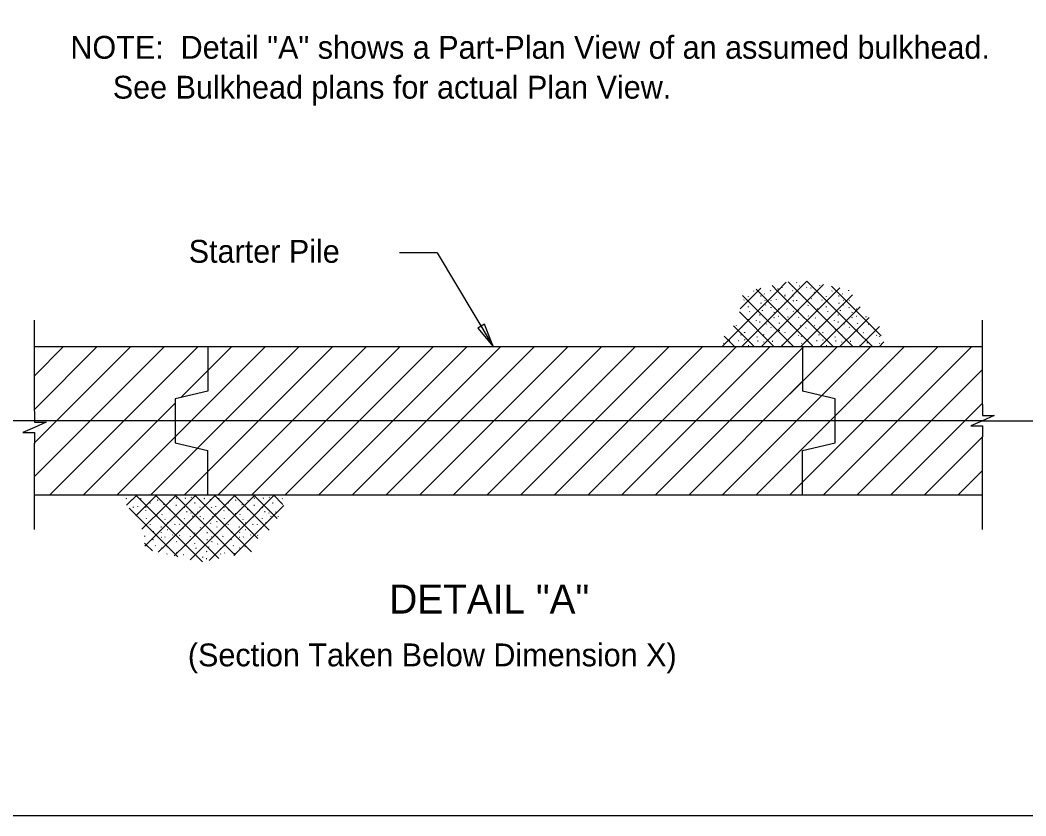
# Model space of a CAD drawing. Extents: x 111162.5 to 111216.6, y 110741.1 to 110776.1.
# Drawn here: x 111166.92 to 111173.58, y 110754.44 to 110759.7 of the extents above; entities that cross this region are included whole.
import ezdxf

# ---------------------------------------------------------------- set-up
doc = ezdxf.new("R2010")
doc.units = 0
for name, color, linetype in [('Patterning', 7, 'Continuous'), ('PlotBorder_dp', 7, 'Continuous'), ('SheetBorder_dp', 7, 'Continuous'), ('TextMisc', 7, 'Continuous'), ('Viewport', 7, 'Continuous')]:
    doc.layers.add(name, color=color, linetype=linetype)

msp = doc.modelspace()

# ---------------------------------------------------------------- linework, layer by layer
at = {"layer": 'Patterning'}
for p, q in [((111169.6835, 110758.1634), (111169.4336, 110758.1634)), ((111169.6835, 110758.1634), (111170.0546, 110757.5448)), ((111167.0161, 110757.1155), (111167.0161, 110757.7198)), ((111173.2935, 110757.1597), (111173.2935, 110757.7198)), ((111173.2935, 110756.3334), (111173.2935, 110756.9491)), ((111167.0161, 110756.3334), (111167.0161, 110756.9048))]:
    msp.add_line(p, q, dxfattribs=at)
msp.add_lwpolyline([(111170.0546, 110757.5448), (111169.9969, 110757.6923), (111169.9515, 110757.6651)], close=True, dxfattribs=at)
for points in [[(111173.2935, 110757.1595), (111173.2935, 110757.087), (111173.371, 110757.087), (111173.2935, 110757.0532), (111173.216, 110757.0195), (111173.2935, 110757.0195), (111173.2935, 110756.947)], [(111167.0161, 110757.1152), (111167.0161, 110757.0427), (111167.0936, 110757.0427), (111167.0161, 110757.009), (111166.9386, 110756.9752), (111167.0161, 110756.9752), (111167.0161, 110756.9027)]]:
    msp.add_lwpolyline(points, dxfattribs=at)
at = {"layer": 'PlotBorder_dp'}
for p, q in [((111167.0161, 110757.5448), (111172.102, 110757.5448)), ((111168.1646, 110757.5448), (111168.1646, 110757.2495)), ((111172.102, 110757.5448), (111172.102, 110757.2495)), ((111172.102, 110757.5448), (111173.2935, 110757.5448)), ((111168.1646, 110757.2495), (111167.948, 110757.1983)), ((111172.3186, 110757.1983), (111172.102, 110757.2495)), ((111167.948, 110757.1983), (111167.948, 110756.9069)), ((111172.3186, 110756.9069), (111172.3186, 110757.1983)), ((111167.948, 110756.9069), (111168.1646, 110756.8558)), ((111172.102, 110756.8558), (111172.3186, 110756.9069)), ((111168.1646, 110756.5605), (111168.1646, 110756.8558)), ((111172.102, 110756.5605), (111172.102, 110756.8558)), ((111172.102, 110756.5605), (111167.0161, 110756.5605)), ((111173.2935, 110756.5605), (111172.102, 110756.5605))]:
    msp.add_line(p, q, dxfattribs=at)
at = {"layer": 'TextMisc'}
for p, q in [((111171.9362, 110757.9116), (111171.9001, 110757.9478)), ((111171.9362, 110757.7813), (111172.1316, 110757.9767)), ((111171.9362, 110757.9116), (111171.9939, 110757.9693)), ((111171.9362, 110757.6511), (111172.2399, 110757.9549)), ((111171.9599, 110757.5445), (111172.3483, 110757.933)), ((111171.9667, 110757.9319), (111171.9675, 110757.9348)), ((111172.4343, 110757.5437), (111172.006, 110757.972)), ((111172.063, 110757.9649), (111172.0638, 110757.9679)), ((111172.0811, 110757.9431), (111172.0788, 110757.9438)), ((111172.1284, 110757.9326), (111172.1299, 110757.9356)), ((111172.4571, 110757.6511), (111172.1315, 110757.9767)), ((111172.1579, 110757.9309), (111172.1586, 110757.934)), ((111172.2167, 110757.9461), (111172.2159, 110757.9476)), ((111172.4571, 110757.7813), (111172.2946, 110757.9438)), ((111171.57, 110757.5452), (111171.9362, 110757.9116)), ((111171.6882, 110757.7937), (111171.825, 110757.9306)), ((111171.9362, 110757.6511), (111171.7044, 110757.883)), ((111171.7442, 110757.8746), (111171.7449, 110757.8777)), ((111171.7798, 110757.9096), (111171.7806, 110757.9125)), ((111171.9362, 110757.7813), (111171.7941, 110757.9235)), ((111171.8276, 110757.8777), (111171.8238, 110757.8769)), ((111171.8502, 110757.8905), (111171.8479, 110757.8927)), ((111171.8908, 110757.9138), (111171.8916, 110757.9168)), ((111172.3039, 110757.5439), (111171.9362, 110757.9116)), ((111171.9397, 110757.9235), (111171.9412, 110757.9273)), ((111171.9855, 110757.8784), (111171.9871, 110757.8815)), ((111171.9871, 110757.8837), (111171.9878, 110757.8868)), ((111172.0389, 110757.9145), (111172.0351, 110757.9138)), ((111172.04, 110757.8767), (111172.0408, 110757.8797)), ((111172.0811, 110757.8957), (111172.0788, 110757.8965)), ((111172.0898, 110757.5443), (111172.4322, 110757.8867)), ((111172.1817, 110757.9026), (111172.1824, 110757.9056)), ((111172.2611, 110757.8746), (111172.2618, 110757.8777)), ((111172.2967, 110757.9096), (111172.2975, 110757.9125)), ((111172.3445, 110757.8777), (111172.3407, 110757.8769)), ((111172.3671, 110757.8905), (111172.3648, 110757.8927)), ((111172.4077, 110757.9138), (111172.4084, 110757.9168)), ((111171.7141, 110757.8506), (111171.7148, 110757.8536)), ((111171.7442, 110757.8055), (111171.7449, 110757.8085)), ((111171.8276, 110757.8304), (111171.8238, 110757.8296)), ((111171.8546, 110757.8483), (111171.8554, 110757.8514)), ((111171.8572, 110757.8181), (111171.858, 110757.8211)), ((111171.8945, 110757.8483), (111171.8953, 110757.8514)), ((111171.8945, 110757.801), (111171.8953, 110757.804)), ((111171.9298, 110757.8533), (111171.9306, 110757.8562)), ((111171.9855, 110757.8311), (111171.9871, 110757.8341)), ((111172.0419, 110757.8461), (111172.0389, 110757.8453)), ((111172.0645, 110757.8476), (111172.0652, 110757.8506)), ((111172.1134, 110757.8612), (111172.1141, 110757.8642)), ((111172.1402, 110757.8168), (111172.1416, 110757.8198)), ((111172.1596, 110757.859), (111172.1611, 110757.862)), ((111172.231, 110757.8506), (111172.2317, 110757.8536)), ((111172.2611, 110757.8055), (111172.2618, 110757.8085)), ((111172.3445, 110757.8304), (111172.3407, 110757.8296)), ((111172.3715, 110757.8483), (111172.3723, 110757.8514)), ((111172.3741, 110757.8181), (111172.3749, 110757.8211)), ((111172.4114, 110757.8483), (111172.4122, 110757.8514)), ((111172.4114, 110757.801), (111172.4122, 110757.804)), ((111172.4571, 110757.7813), (111172.4837, 110757.8079)), ((111171.9125, 110757.5446), (111171.6844, 110757.7728)), ((111171.6999, 110757.545), (111171.9362, 110757.7814)), ((111171.7517, 110757.7735), (111171.7525, 110757.7765)), ((111171.8223, 110757.7528), (111171.8179, 110757.7521)), ((111171.8359, 110757.7815), (111171.8367, 110757.7844)), ((111171.9148, 110757.7702), (111171.9156, 110757.7731)), ((111171.9148, 110757.7348), (111171.9156, 110757.7378)), ((111172.1734, 110757.5441), (111171.9362, 110757.7814)), ((111171.9427, 110757.7912), (111171.9397, 110757.7905)), ((111171.9427, 110757.7438), (111171.9397, 110757.7431)), ((111172.0006, 110757.7912), (111171.9983, 110757.7935)), ((111172.0058, 110757.7394), (111172.0066, 110757.7424)), ((111172.0397, 110757.7754), (111172.0412, 110757.7784)), ((111172.078, 110757.7852), (111172.075, 110757.7837)), ((111172.078, 110757.7378), (111172.075, 110757.7364)), ((111172.1417, 110757.7461), (111172.1402, 110757.7483)), ((111172.1889, 110757.7319), (111172.1851, 110757.7311)), ((111172.2009, 110757.7935), (111172.1994, 110757.7957)), ((111172.2198, 110757.544), (111172.4571, 110757.7814)), ((111172.2686, 110757.7735), (111172.2694, 110757.7765)), ((111172.3392, 110757.7528), (111172.3348, 110757.7521)), ((111172.3528, 110757.7815), (111172.3536, 110757.7844)), ((111172.4317, 110757.7702), (111172.4325, 110757.7731)), ((111172.4317, 110757.7348), (111172.4325, 110757.7378)), ((111172.4596, 110757.7912), (111172.4566, 110757.7905)), ((111172.4596, 110757.7438), (111172.4566, 110757.7431)), ((111172.6234, 110757.615), (111172.4571, 110757.7814)), ((111172.4571, 110757.6511), (111172.5424, 110757.7365)), ((111172.5227, 110757.7394), (111172.5235, 110757.7424)), ((111171.7821, 110757.5449), (111171.6451, 110757.6818)), ((111171.6651, 110757.6809), (111171.6659, 110757.6839)), ((111171.7013, 110757.6731), (111171.702, 110757.6762)), ((111171.7412, 110757.7228), (111171.7419, 110757.7258)), ((111171.7968, 110757.7145), (111171.7975, 110757.7175)), ((111171.8223, 110757.7055), (111171.8179, 110757.7047)), ((111171.8637, 110757.6927), (111171.863, 110757.6942)), ((111171.8945, 110757.6694), (111171.8953, 110757.6724)), ((111171.9494, 110757.6965), (111171.9502, 110757.7002)), ((111172.0216, 110757.6897), (111172.0201, 110757.6905)), ((111172.0878, 110757.6814), (111172.0871, 110757.6829)), ((111172.1246, 110757.6649), (111172.1253, 110757.6679)), ((111172.182, 110757.6809), (111172.1828, 110757.6839)), ((111172.2182, 110757.6731), (111172.2189, 110757.6762)), ((111172.2581, 110757.7228), (111172.2588, 110757.7258)), ((111172.3137, 110757.7145), (111172.3144, 110757.7175)), ((111172.3392, 110757.7055), (111172.3348, 110757.7047)), ((111172.3806, 110757.6927), (111172.3799, 110757.6942)), ((111172.4114, 110757.6694), (111172.4122, 110757.6724)), ((111172.4663, 110757.6965), (111172.4671, 110757.7002)), ((111172.4797, 110757.5436), (111172.6119, 110757.6757)), ((111172.5385, 110757.6897), (111172.537, 110757.6905)), ((111171.6516, 110757.5451), (111171.5838, 110757.613)), ((111171.6945, 110757.6205), (111171.6953, 110757.6235)), ((111171.7201, 110757.6356), (111171.7209, 110757.6386)), ((111171.802, 110757.6543), (111171.8035, 110757.6574)), ((111171.802, 110757.607), (111171.8035, 110757.61)), ((111171.8299, 110757.5448), (111171.9362, 110757.6511)), ((111171.8464, 110757.6205), (111171.8464, 110757.6235)), ((111171.8637, 110757.6453), (111171.863, 110757.6468)), ((111172.043, 110757.5444), (111171.9362, 110757.6511)), ((111171.9494, 110757.6491), (111171.9502, 110757.6528)), ((111171.9871, 110757.634), (111171.9878, 110757.6371)), ((111172.0344, 110757.6168), (111172.0307, 110757.616)), ((111172.0562, 110757.6626), (111172.0532, 110757.6612)), ((111172.0765, 110757.6183), (111172.075, 110757.6205)), ((111172.0953, 110757.6115), (111172.0968, 110757.6145)), ((111172.2114, 110757.6205), (111172.2122, 110757.6235)), ((111172.237, 110757.6356), (111172.2377, 110757.6386)), ((111172.3189, 110757.6543), (111172.3204, 110757.6574)), ((111172.3189, 110757.607), (111172.3204, 110757.61)), ((111172.3498, 110757.5438), (111172.4571, 110757.6511)), ((111172.3633, 110757.6205), (111172.3633, 110757.6235)), ((111172.3806, 110757.6453), (111172.3799, 110757.6468)), ((111172.5648, 110757.5434), (111172.4571, 110757.6511)), ((111172.4663, 110757.6491), (111172.4671, 110757.6528)), ((111172.504, 110757.634), (111172.5047, 110757.6371)), ((111172.5513, 110757.6168), (111172.5476, 110757.616)), ((111172.5731, 110757.6626), (111172.5701, 110757.6612)), ((111172.5934, 110757.6183), (111172.5919, 110757.6205)), ((111172.6122, 110757.6115), (111172.6137, 110757.6145)), ((111167.0161, 110757.3514), (111167.2096, 110757.5448)), ((111167.0161, 110757.1286), (111167.4323, 110757.5448)), ((111167.0161, 110756.9059), (111167.655, 110757.5448)), ((111167.0161, 110756.6832), (111167.8778, 110757.5448)), ((111167.1161, 110756.5605), (111168.1005, 110757.5448)), ((111167.9157, 110756.9146), (111168.546, 110757.5448)), ((111167.9856, 110757.2072), (111168.3232, 110757.5448)), ((111168.0959, 110756.872), (111168.7687, 110757.5448)), ((111168.1646, 110756.7179), (111168.9915, 110757.5448)), ((111168.2298, 110756.5605), (111169.2142, 110757.5448)), ((111168.4526, 110756.5605), (111169.4369, 110757.5448)), ((111168.6753, 110756.5605), (111169.6596, 110757.5448)), ((111168.898, 110756.5605), (111169.8824, 110757.5448)), ((111169.1208, 110756.5605), (111170.1052, 110757.5448)), ((111169.3435, 110756.5605), (111170.3279, 110757.5448)), ((111169.5662, 110756.5605), (111170.5506, 110757.5448)), ((111169.789, 110756.5605), (111170.7734, 110757.5448)), ((111170.0117, 110756.5605), (111170.9961, 110757.5448)), ((111170.2344, 110756.5605), (111171.2188, 110757.5448)), ((111170.4572, 110756.5605), (111171.4416, 110757.5448)), ((111170.6799, 110756.5605), (111171.6643, 110757.5448)), ((111170.9027, 110756.5605), (111171.887, 110757.5448)), ((111171.1254, 110756.5605), (111172.1098, 110757.5448)), ((111171.5784, 110757.5641), (111171.5799, 110757.5672)), ((111171.6218, 110757.5822), (111171.6181, 110757.5814)), ((111171.681, 110757.5822), (111171.6772, 110757.5814)), ((111171.7201, 110757.5874), (111171.7209, 110757.5905)), ((111171.7457, 110757.5498), (111171.7412, 110757.5498)), ((111171.8073, 110757.5799), (111171.8043, 110757.5792)), ((111171.8464, 110757.5731), (111171.8464, 110757.5761)), ((111171.905, 110757.5784), (111171.9013, 110757.5776)), ((111171.9645, 110757.5506), (111171.9667, 110757.5535)), ((111172.0134, 110757.5687), (111172.0149, 110757.5716)), ((111172.0149, 110757.5672), (111172.0156, 110757.5702)), ((111172.0163, 110756.5605), (111173.0007, 110757.5448)), ((111172.0171, 110757.2294), (111172.3325, 110757.5448)), ((111172.0849, 110756.8517), (111172.778, 110757.5448)), ((111172.0953, 110757.5641), (111172.0968, 110757.5672)), ((111172.1387, 110757.5822), (111172.1349, 110757.5814)), ((111172.1979, 110757.5822), (111172.1941, 110757.5814)), ((111172.2297, 110757.2193), (111172.5553, 110757.5448)), ((111172.237, 110757.5874), (111172.2377, 110757.5905)), ((111172.2391, 110756.5605), (111173.2234, 110757.5448)), ((111172.2625, 110757.5498), (111172.2581, 110757.5498)), ((111172.3242, 110757.5799), (111172.3212, 110757.5792)), ((111172.3633, 110757.5731), (111172.3633, 110757.5761)), ((111172.4219, 110757.5784), (111172.4182, 110757.5776)), ((111172.4814, 110757.5506), (111172.4836, 110757.5535)), ((111172.5303, 110757.5687), (111172.5318, 110757.5716)), ((111172.5318, 110757.5672), (111172.5325, 110757.5702)), ((111172.6097, 110757.5433), (111172.641, 110757.5747)), ((111172.6122, 110757.5641), (111172.6137, 110757.5672)), ((111172.4618, 110756.5605), (111173.2935, 110757.3921)), ((111171.3482, 110756.5605), (111172.102, 110757.3143)), ((111171.5709, 110756.5605), (111172.2298, 110757.2193)), ((111167.3388, 110756.5605), (111167.948, 110757.1696)), ((111172.6846, 110756.5605), (111173.2935, 110757.1694)), ((111167.0161, 110757.0526), (111166.6224, 110757.0526)), ((111173.2935, 110757.0526), (111167.0161, 110757.0526)), ((111173.2935, 110757.0526), (111173.6872, 110757.0526)), ((111167.5616, 110756.5605), (111167.948, 110756.9468)), ((111172.9073, 110756.5605), (111173.2935, 110756.9466)), ((111167.7844, 110756.5605), (111168.0959, 110756.872)), ((111168.0071, 110756.5605), (111168.3451, 110756.8984)), ((111171.7936, 110756.5605), (111172.0914, 110756.8583)), ((111173.13, 110756.5605), (111173.2935, 110756.724)), ((111167.625, 110756.5378), (111167.622, 110756.5371)), ((111167.627, 110756.4937), (111167.6935, 110756.5602)), ((111167.6642, 110756.531), (111167.6642, 110756.534)), ((111167.6884, 110756.4248), (111167.8239, 110756.5604)), ((111167.8864, 110756.3624), (111167.6887, 110756.5602)), ((111167.7227, 110756.5363), (111167.719, 110756.5355)), ((111167.8864, 110756.4926), (111167.8186, 110756.5604)), ((111167.8864, 110756.2322), (111168.2153, 110756.5611)), ((111167.8864, 110756.3624), (111168.0848, 110756.5609)), ((111167.8864, 110756.4926), (111167.9544, 110756.5606)), ((111168.277, 110756.2322), (111167.9487, 110756.5606)), ((111167.9564, 110756.5401), (111167.9527, 110756.5393)), ((111168.0156, 110756.5401), (111168.0118, 110756.5393)), ((111168.0166, 110756.2322), (111168.3457, 110756.5614)), ((111168.0547, 110756.5453), (111168.0555, 110756.5483)), ((111168.407, 110756.2325), (111168.0786, 110756.5609)), ((111168.1419, 110756.5378), (111168.1389, 110756.5371)), ((111168.1811, 110756.531), (111168.1811, 110756.534)), ((111168.4072, 110756.3624), (111168.2086, 110756.5611)), ((111168.2396, 110756.5363), (111168.2359, 110756.5355)), ((111168.4072, 110756.4926), (111168.3385, 110756.5613)), ((111168.4072, 110756.3624), (111168.6066, 110756.5618)), ((111168.4072, 110756.4926), (111168.4762, 110756.5616)), ((111168.6246, 110756.4055), (111168.4685, 110756.5616)), ((111168.4733, 110756.5401), (111168.4696, 110756.5393)), ((111168.5325, 110756.5401), (111168.5287, 110756.5393)), ((111168.5716, 110756.5453), (111168.5724, 110756.5483)), ((111168.6609, 110756.4994), (111168.5985, 110756.5618)), ((111168.6588, 110756.5378), (111168.6558, 110756.5371)), ((111168.7294, 110756.5611), (111168.7284, 110756.5621)), ((111167.8861, 110756.2325), (111167.6431, 110756.4755)), ((111167.6724, 110756.4799), (111167.6731, 110756.4829)), ((111167.7017, 110756.4844), (111167.701, 110756.4859)), ((111167.7285, 110756.3347), (111167.8864, 110756.4927)), ((111167.7544, 110756.4799), (111167.7551, 110756.4829)), ((111167.7822, 110756.5085), (111167.7845, 110756.5114)), ((111167.8311, 110756.5265), (111167.8326, 110756.5295)), ((111167.8326, 110756.525), (111167.8333, 110756.528)), ((111167.8739, 110756.4965), (111167.8724, 110756.4987)), ((111168.1468, 110756.2322), (111167.8864, 110756.4927)), ((111167.9153, 110756.4664), (111167.9123, 110756.4664)), ((111167.913, 110756.522), (111167.9145, 110756.525)), ((111167.9564, 110756.4927), (111167.9527, 110756.4919)), ((111168.01, 110756.4769), (111168.0107, 110756.4799)), ((111168.0803, 110756.5077), (111168.0758, 110756.5077)), ((111168.1141, 110756.4784), (111168.1126, 110756.4791)), ((111168.1468, 110756.2322), (111168.4072, 110756.4927)), ((111168.1893, 110756.4799), (111168.19, 110756.4829)), ((111168.2186, 110756.4844), (111168.2179, 110756.4859)), ((111168.2713, 110756.4799), (111168.272, 110756.4829)), ((111168.2991, 110756.5085), (111168.3014, 110756.5114)), ((111168.348, 110756.5265), (111168.3495, 110756.5295)), ((111168.3495, 110756.525), (111168.3502, 110756.528)), ((111168.3908, 110756.4965), (111168.3893, 110756.4987)), ((111168.5705, 110756.3294), (111168.4072, 110756.4927)), ((111168.4072, 110756.2322), (111168.6667, 110756.4917)), ((111168.4322, 110756.4664), (111168.4292, 110756.4664)), ((111168.4299, 110756.522), (111168.4314, 110756.525)), ((111168.4733, 110756.4927), (111168.4696, 110756.4919)), ((111168.5269, 110756.4769), (111168.5276, 110756.4799)), ((111168.5972, 110756.5077), (111168.5927, 110756.5077)), ((111168.631, 110756.4784), (111168.6295, 110756.4791)), ((111167.7017, 110756.4371), (111167.701, 110756.4386)), ((111167.7544, 110756.4558), (111167.7551, 110756.4588)), ((111167.7574, 110756.4055), (111167.7589, 110756.4092)), ((111167.7822, 110756.4611), (111167.7845, 110756.4641)), ((111167.8289, 110756.422), (111167.8303, 110756.4251)), ((111167.8326, 110756.4378), (111167.8333, 110756.4408)), ((111167.8612, 110756.4317), (111167.8627, 110756.4355)), ((111167.8807, 110756.3994), (111167.8815, 110756.4025)), ((111167.9123, 110756.4641), (111167.9116, 110756.4656)), ((111167.9461, 110756.4145), (111167.9476, 110756.4175)), ((111168.0085, 110756.404), (111168.0092, 110756.407)), ((111168.0277, 110756.4506), (111168.0239, 110756.4498)), ((111168.0344, 110756.428), (111168.034, 110756.4288)), ((111168.0532, 110756.4415), (111168.054, 110756.4446)), ((111168.0645, 110756.4197), (111168.066, 110756.4235)), ((111168.0976, 110756.4483), (111168.0983, 110756.4513)), ((111168.1149, 110756.4167), (111168.1164, 110756.4197)), ((111168.1389, 110756.404), (111168.1352, 110756.4032)), ((111168.1983, 110756.4197), (111168.1946, 110756.4182)), ((111168.2186, 110756.4371), (111168.2179, 110756.4386)), ((111168.2713, 110756.4558), (111168.272, 110756.4588)), ((111168.2743, 110756.4055), (111168.2758, 110756.4092)), ((111168.2991, 110756.4611), (111168.3014, 110756.4641)), ((111168.3458, 110756.422), (111168.3472, 110756.4251)), ((111168.3495, 110756.4378), (111168.3502, 110756.4408)), ((111168.3781, 110756.4317), (111168.3796, 110756.4355)), ((111168.3976, 110756.3994), (111168.3984, 110756.4025)), ((111168.4292, 110756.4641), (111168.4284, 110756.4656)), ((111168.463, 110756.4145), (111168.4645, 110756.4175)), ((111168.5254, 110756.404), (111168.5261, 110756.407)), ((111168.5446, 110756.4506), (111168.5408, 110756.4498)), ((111168.5513, 110756.428), (111168.5509, 110756.4288)), ((111168.5701, 110756.4415), (111168.5709, 110756.4446)), ((111168.5814, 110756.4197), (111168.5829, 110756.4235)), ((111168.6145, 110756.4483), (111168.6152, 110756.4513)), ((111168.6318, 110756.4167), (111168.6333, 110756.4197)), ((111167.7562, 110756.2322), (111167.8864, 110756.3624)), ((111167.7574, 110756.3581), (111167.7589, 110756.3618)), ((111167.7845, 110756.3664), (111167.7852, 110756.3693)), ((111167.8567, 110756.349), (111167.8528, 110756.3483)), ((111168.0166, 110756.2322), (111167.8864, 110756.3624)), ((111167.8988, 110756.3777), (111167.8965, 110756.3784)), ((111167.9461, 110756.3671), (111167.9476, 110756.3701)), ((111167.9756, 110756.3654), (111167.9764, 110756.3685)), ((111167.9994, 110756.3372), (111168.0001, 110756.3402)), ((111168.0344, 110756.3807), (111168.0337, 110756.3822)), ((111168.1144, 110756.3441), (111168.1152, 110756.3471)), ((111168.1848, 110756.3724), (111168.1825, 110756.3747)), ((111168.2247, 110756.3852), (111168.2255, 110756.3881)), ((111168.2255, 110756.3483), (111168.2262, 110756.3514)), ((111168.2743, 110756.3581), (111168.2758, 110756.3618)), ((111168.277, 110756.2322), (111168.4072, 110756.3624)), ((111168.3014, 110756.3664), (111168.3021, 110756.3693)), ((111168.3736, 110756.349), (111168.3697, 110756.3483)), ((111168.4963, 110756.2733), (111168.4072, 110756.3624)), ((111168.4157, 110756.3777), (111168.4134, 110756.3784)), ((111168.463, 110756.3671), (111168.4645, 110756.3701)), ((111168.4925, 110756.3654), (111168.4933, 110756.3685)), ((111168.5163, 110756.3372), (111168.517, 110756.3402)), ((111168.5513, 110756.3807), (111168.5505, 110756.3822)), ((111167.7476, 110756.2878), (111167.7483, 110756.2907)), ((111167.8032, 110756.3129), (111167.8048, 110756.316)), ((111167.8032, 110756.2656), (111167.8048, 110756.2686)), ((111167.8048, 110756.3182), (111167.8055, 110756.3213)), ((111167.8597, 110756.2807), (111167.8567, 110756.2799)), ((111167.8577, 110756.3113), (111167.8585, 110756.3142)), ((111167.8822, 110756.2822), (111167.8829, 110756.2851)), ((111167.8988, 110756.3303), (111167.8965, 110756.331)), ((111167.9311, 110756.2957), (111167.9319, 110756.2987)), ((111167.9773, 110756.2935), (111167.9788, 110756.2965)), ((111168.0487, 110756.2851), (111168.0494, 110756.2881)), ((111168.0788, 110756.3092), (111168.0795, 110756.3122)), ((111168.1622, 110756.3122), (111168.1585, 110756.3115)), ((111168.1848, 110756.3251), (111168.1825, 110756.3273)), ((111168.1893, 110756.2829), (111168.19, 110756.2859)), ((111168.2292, 110756.2829), (111168.2299, 110756.2859)), ((111168.2644, 110756.2878), (111168.2652, 110756.2907)), ((111168.3201, 110756.3129), (111168.3217, 110756.316)), ((111168.3201, 110756.2656), (111168.3217, 110756.2686)), ((111168.3217, 110756.3182), (111168.3224, 110756.3213)), ((111168.3766, 110756.2807), (111168.3736, 110756.2799)), ((111168.3746, 110756.3113), (111168.3754, 110756.3142)), ((111168.3991, 110756.2822), (111168.3998, 110756.2851)), ((111168.4157, 110756.3303), (111168.4134, 110756.331)), ((111168.448, 110756.2957), (111168.4488, 110756.2987)), ((111168.4942, 110756.2935), (111168.4957, 110756.2965)), ((111167.7562, 110756.2322), (111167.745, 110756.2434)), ((111167.7484, 110756.2244), (111167.7562, 110756.2322)), ((111167.7971, 110756.1913), (111167.7562, 110756.2322)), ((111167.7604, 110756.2258), (111167.7574, 110756.225)), ((111167.8183, 110756.2258), (111167.816, 110756.228)), ((111167.8365, 110756.1823), (111167.8864, 110756.2322)), ((111167.8574, 110756.21), (111167.8589, 110756.2129)), ((111167.966, 110756.1526), (111167.8864, 110756.2322)), ((111167.8957, 110756.2197), (111167.8927, 110756.2182)), ((111167.9424, 110756.158), (111168.0166, 110756.2322)), ((111167.9579, 110756.2514), (111167.9593, 110756.2544)), ((111168.1296, 110756.1192), (111168.0166, 110756.2322)), ((111168.0186, 110756.228), (111168.0171, 110756.2303)), ((111168.0483, 110756.1337), (111168.1468, 110756.2322)), ((111168.0788, 110756.24), (111168.0795, 110756.243)), ((111168.0863, 110756.2081), (111168.0871, 110756.211)), ((111168.238, 110756.141), (111168.1468, 110756.2322)), ((111168.1622, 110756.2649), (111168.1585, 110756.2641)), ((111168.1705, 110756.216), (111168.1713, 110756.2189)), ((111168.1727, 110756.1279), (111168.277, 110756.2322)), ((111168.1918, 110756.2527), (111168.1926, 110756.2556)), ((111168.2292, 110756.2355), (111168.2299, 110756.2385)), ((111168.2494, 110756.2047), (111168.2502, 110756.2077)), ((111168.2773, 110756.2258), (111168.2743, 110756.225)), ((111168.3463, 110756.1629), (111168.277, 110756.2322)), ((111168.3352, 110756.2258), (111168.3329, 110756.228)), ((111168.3358, 110756.1608), (111168.4072, 110756.2322)), ((111168.3743, 110756.21), (111168.3758, 110756.2129)), ((111168.4547, 110756.1848), (111168.4072, 110756.2322)), ((111168.4126, 110756.2197), (111168.4096, 110756.2182)), ((111167.8957, 110756.1723), (111167.8927, 110756.1709)), ((111167.9594, 110756.1807), (111167.9579, 110756.1829)), ((111168.0066, 110756.1664), (111168.0028, 110756.1656)), ((111168.0758, 110756.1573), (111168.0765, 110756.1603)), ((111168.1314, 110756.149), (111168.1322, 110756.1521)), ((111168.157, 110756.1874), (111168.1525, 110756.1866)), ((111168.157, 110756.14), (111168.1525, 110756.1392)), ((111168.2494, 110756.1693), (111168.2502, 110756.1723)), ((111168.2773, 110756.1784), (111168.2743, 110756.1776)), ((111168.3404, 110756.1739), (111168.3412, 110756.1769))]:
    msp.add_line(p, q, dxfattribs=at)
at = {"layer": 'Viewport'}
msp.add_lwpolyline([(111162.5509, 110774.2382), (111193.3509, 110774.2382), (111193.3509, 110754.4382), (111162.5509, 110754.4382)], close=True, dxfattribs=at)

# ---------------------------------------------------------------- texts
at = {"layer": 'Patterning'}
for s, p in [('NOTE:  Detail "A" shows a Part-Plan View of an assumed bulkhead. ', (111167.2543, 110759.4487)), ('     See Bulkhead plans for actual Plan View.            ', (111167.2543, 110759.1847))]:
    msp.add_text(s, height=0.1512, dxfattribs=at).set_placement(p)
at = {"layer": 'SheetBorder_dp'}
for s, height, p in [('Starter Pile', 0.1512, (111168.0379, 110758.0986)), ('DETAIL "A"', 0.192, (111169.3661, 110755.777)), ('(Section Taken Below Dimension X)', 0.1512, (111168.0323, 110755.4278))]:
    msp.add_text(s, height=height, dxfattribs=at).set_placement(p)

doc.saveas('drawing.dxf')
